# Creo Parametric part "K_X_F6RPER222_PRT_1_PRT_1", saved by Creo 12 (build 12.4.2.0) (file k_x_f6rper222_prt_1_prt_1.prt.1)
Units: Custom; MM, KILOGRAM, SECS

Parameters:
  PTC_WM_ITERATION = "0"
  PTC_WM_VERSION = "-.0"
  PTC_WM_LIFECYCLE_STATE = "In Work"
  PTC_WM_LIFECYCLE = "MO_CADDocument"
  PTC_WM_CREATED_BY = "Maximilian Roepper (Z0017RMS: MO)"
  PTC_WM_CREATED_ON = "18-Sep-26 11:36:42 AM"
  PTC_WM_MODIFIED_BY = "Maximilian Roepper (Z0017RMS: MO)"
  PTC_WM_MODIFIED_ON = "18-Sep-26 11:36:46 AM"
  PDMLINKNUMBER = "PDM000071455331"
  PTC_WM_NAME = "k_x_f6rper222_prt_1_prt_1.prt"
  PTC_WM_NUMBER = "PDM000071455331"

Other parameters: WEIGHT, WEIGHT_FACTOR, WEIGHT_ADD, _MASS_TEMP, _DIFF_TEMP, MC_ERRORS, SUPPLIER

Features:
  1. coordinate system
  2. datum plane "PRT_YZ"
  3. datum plane "PRT_XY"
  4. datum plane "PRT_XZ"
  5. coordinate system
  6. datum axis
  7. datum axis
  8. datum axis
  9. coordinate system
  10. imported feature
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
Other named items: PRT, SIEMENS_MO, DRW_VIEW_ORG, PRT_X, PRT_Y, PRT_Z, CS0, ROUGH_GROB

Layers: 00_STD_CSYS-KSYS, 01_STD_PLANES-EBENEN, 02_STD_AXES-ACHSEN, 03_STD_CSYS-KSYS, 24_IMPORT_FEAT-IMPORT_KE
